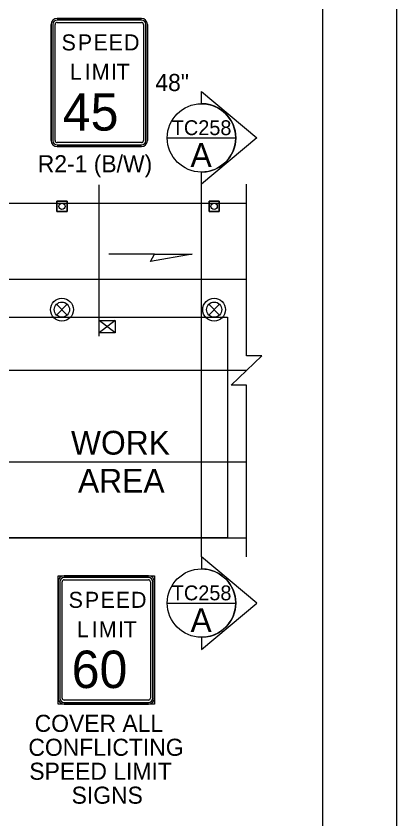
# Model space of a CAD drawing. Extents: x 99999 to 100116, y 99995 to 100013.
# Drawn here: x 100094.461 to 100096.062, y 100005.607 to 100008.987 of the extents above; entities that cross this region are included whole.
import ezdxf

# ---------------------------------------------------------------- set-up
doc = ezdxf.new("R2010")
doc.units = 0
for name, color, linetype in [('RD_MK_LineEdgeYellow', 7, 'Continuous'), ('RD_MK_LineLane', 7, 'Continuous'), ('SH_GI_PlotLimits', 7, 'Continuous'), ('SH_GI_SectionCut', 7, 'Continuous'), ('SH_GI_SheetBorder', 7, 'Continuous'), ('TR_SN_ConstructionSigns', 7, 'Continuous'), ('TR_WZ_PortableSignMount5ftMinBlk-Wht', 7, 'Continuous'), ('TR_WZ_TrafficCone', 7, 'Continuous'), ('TR_WZ_TrafficSafetyDrum', 7, 'Continuous'), ('TR_WZ_WorkAreaLabel', 7, 'Continuous'), ('TR_WZ_WorkZoneDetails', 7, 'Continuous')]:
    doc.layers.add(name, color=color, linetype=linetype)

msp = doc.modelspace()

# ---------------------------------------------------------------- linework, layer by layer
at = {"layer": 'RD_MK_LineEdgeYellow'}
for p, q in [((100092.5055, 100007.8789), (100095.43, 100007.8789)), ((100088.195, 100007.1109), (100095.43, 100007.1109))]:
    msp.add_line(p, q, dxfattribs=at)
at = {"layer": 'RD_MK_LineLane'}
msp.add_lwpolyline([(100095.43, 100007.4949), (100088.195, 100007.4949)], dxfattribs=at)
at = {"layer": 'SH_GI_PlotLimits'}
msp.add_lwpolyline([(100079.0625, 99999.6875), (100096.0625, 99999.6875), (100096.0625, 100010.6875), (100079.0625, 100010.6875)], close=True, dxfattribs=at)
at = {"layer": 'SH_GI_SectionCut'}
for p, q in [((100095.2407, 100008.6178), (100095.2407, 100008.6687)), ((100095.2407, 100008.6687), (100095.4733, 100008.4738)), ((100095.4733, 100008.4738), (100095.2407, 100008.2789)), ((100095.2407, 100008.2789), (100095.2407, 100008.3298)), ((100095.2407, 100006.7109), (100095.2407, 100008.2789)), ((100095.2407, 100006.7109), (100095.2407, 100006.66)), ((100095.4733, 100006.516), (100095.2407, 100006.7109)), ((100095.2407, 100006.3211), (100095.4733, 100006.516)), ((100095.2407, 100006.372), (100095.2407, 100006.3211))]:
    msp.add_line(p, q, dxfattribs=at)
for points in [[(100095.0967, 100008.4738), (100095.3847, 100008.4738)], [(100095.0967, 100006.516), (100095.3847, 100006.516)]]:
    msp.add_lwpolyline(points, dxfattribs=at)
for centre in [(100095.2407, 100008.4738), (100095.2407, 100006.516)]:
    msp.add_circle(centre, 0.144, dxfattribs=at)
for centre in [(100095.2407, 100008.4738), (100095.2407, 100006.516)]:
    msp.add_arc(centre, 0.144, 269.9978, 90.0022, dxfattribs=at)
at = {"layer": 'SH_GI_SheetBorder'}
msp.add_line((100095.75, 100010.375), (100095.75, 100000), dxfattribs=at)
at = {"layer": 'TR_SN_ConstructionSigns'}
for p, q in [((100094.6337, 100008.9769), (100094.9881, 100008.9769)), ((100094.9881, 100008.9769), (100094.6337, 100008.9769)), ((100094.9881, 100008.9699), (100094.6337, 100008.9699)), ((100094.6337, 100008.96), (100094.9881, 100008.96)), ((100094.6084, 100008.4622), (100094.6084, 100008.9516)), ((100094.6084, 100008.9516), (100094.6084, 100008.4622)), ((100094.6154, 100008.9516), (100094.6154, 100008.4622)), ((100094.6253, 100008.4622), (100094.6253, 100008.9516)), ((100094.9965, 100008.9516), (100094.9965, 100008.4622)), ((100095.0064, 100008.4622), (100095.0064, 100008.9516)), ((100095.0134, 100008.9516), (100095.0134, 100008.4622)), ((100095.0134, 100008.4622), (100095.0134, 100008.9516)), ((100094.9881, 100008.4538), (100094.6337, 100008.4538)), ((100094.6337, 100008.4439), (100094.9881, 100008.4439)), ((100094.9881, 100008.4369), (100094.6337, 100008.4369)), ((100094.6337, 100008.4369), (100094.9881, 100008.4369)), ((100094.6633, 100006.6309), (100095.0177, 100006.6309)), ((100095.0177, 100006.6309), (100094.6633, 100006.6309)), ((100095.0177, 100006.6239), (100094.6633, 100006.6239)), ((100094.638, 100006.1162), (100094.638, 100006.6056)), ((100094.638, 100006.6056), (100094.638, 100006.1162)), ((100094.6451, 100006.6056), (100094.6451, 100006.1162)), ((100094.6549, 100006.1162), (100094.6549, 100006.6056)), ((100094.6633, 100006.614), (100095.0177, 100006.614)), ((100095.0261, 100006.6056), (100095.0261, 100006.1162)), ((100095.036, 100006.1162), (100095.036, 100006.6056)), ((100095.043, 100006.6056), (100095.043, 100006.1162)), ((100095.043, 100006.1162), (100095.043, 100006.6056)), ((100095.0177, 100006.1078), (100094.6633, 100006.1078)), ((100094.6633, 100006.0979), (100095.0177, 100006.0979)), ((100095.0177, 100006.0909), (100094.6633, 100006.0909)), ((100094.6633, 100006.0909), (100095.0177, 100006.0909))]:
    msp.add_line(p, q, dxfattribs=at)
msp.add_lwpolyline([(100094.638, 100006.6309), (100095.043, 100006.6309), (100095.043, 100006.0909), (100094.638, 100006.0909)], close=True, dxfattribs=at)
for centre, radius, start, end in [((100094.6337, 100008.9516), 0.0253, 90, 180), ((100094.6337, 100008.9516), 0.0253, 90, 180), ((100094.6337, 100008.9516), 0.0183, 90, 180), ((100094.6337, 100008.9516), 0.00844, 90, 180), ((100094.9881, 100008.9516), 0.0253, 360, 90), ((100094.9881, 100008.9516), 0.0253, 360, 90), ((100094.9881, 100008.9516), 0.0183, 0, 90), ((100094.9881, 100008.9516), 0.00844, 360, 90), ((100094.6337, 100008.4622), 0.0253, 180, 270), ((100094.6337, 100008.4622), 0.0253, 180, 270), ((100094.6337, 100008.4622), 0.0183, 180, 270), ((100094.6337, 100008.4622), 0.00844, 180, 270), ((100094.9881, 100008.4622), 0.0253, 270, 360), ((100094.9881, 100008.4622), 0.0183, 270, 360), ((100094.9881, 100008.4622), 0.00844, 270, 0), ((100094.9881, 100008.4622), 0.0253, 270, 360), ((100094.6633, 100006.6056), 0.0253, 90, 180), ((100094.6633, 100006.6056), 0.0253, 90, 180), ((100094.6633, 100006.6056), 0.0183, 90, 180), ((100095.0177, 100006.6056), 0.0253, 0, 90), ((100095.0177, 100006.6056), 0.0253, 360, 90), ((100095.0177, 100006.6056), 0.0183, 0, 90), ((100094.6633, 100006.6056), 0.00844, 90, 180), ((100095.0177, 100006.6056), 0.00844, 360, 90), ((100094.6633, 100006.1162), 0.0253, 180, 270), ((100094.6633, 100006.1162), 0.0253, 180, 270), ((100094.6633, 100006.1162), 0.0183, 180, 270), ((100094.6633, 100006.1162), 0.00844, 180, 270), ((100095.0177, 100006.1162), 0.0253, 270, 0), ((100095.0177, 100006.1162), 0.0183, 270, 360), ((100095.0177, 100006.1162), 0.00844, 270, 0), ((100095.0177, 100006.1162), 0.0253, 270, 0)]:
    msp.add_arc(centre, radius, start, end, dxfattribs=at)
at = {"layer": 'TR_WZ_PortableSignMount5ftMinBlk-Wht'}
for p, q in [((100094.8109, 100007.6389), (100094.8109, 100007.7189)), ((100094.8776, 100007.7049), (100094.8109, 100007.6529)), ((100094.8776, 100007.6529), (100094.8109, 100007.7049)), ((100094.8443, 100007.6789), (100094.8443, 100007.6789)), ((100094.8444, 100007.679), (100094.8444, 100007.679))]:
    msp.add_line(p, q, dxfattribs=at)
msp.add_lwpolyline([(100094.8776, 100007.7049), (100094.8776, 100007.6529), (100094.8109, 100007.6529), (100094.8109, 100007.7049)], close=True, dxfattribs=at)
at = {"layer": 'TR_WZ_TrafficCone'}
for points in [[(100094.6326, 100008.1642), (100094.6753, 100008.1642), (100094.6753, 100008.2069), (100094.6326, 100008.2069), (100094.6326, 100008.1642)], [(100094.6326, 100008.2069), (100094.6753, 100008.2069), (100094.6753, 100008.1642), (100094.6326, 100008.1642), (100094.6326, 100008.2069)], [(100095.2726, 100008.1642), (100095.3153, 100008.1642), (100095.3153, 100008.2069), (100095.2726, 100008.2069), (100095.2726, 100008.1642)], [(100095.2726, 100008.2069), (100095.3153, 100008.2069), (100095.3153, 100008.1642), (100095.2726, 100008.1642), (100095.2726, 100008.2069)]]:
    msp.add_lwpolyline(points, dxfattribs=at)
for centre in [(100094.6539, 100008.1856), (100095.2939, 100008.1856)]:
    msp.add_circle(centre, 0.0133, dxfattribs=at)
at = {"layer": 'TR_WZ_TrafficSafetyDrum'}
for p, q in [((100094.6313, 100007.7735), (100094.6765, 100007.7283)), ((100094.6765, 100007.7735), (100094.6313, 100007.7283)), ((100095.2713, 100007.7735), (100095.3165, 100007.7283)), ((100095.3165, 100007.7735), (100095.2713, 100007.7283))]:
    msp.add_line(p, q, dxfattribs=at)
for centre, radius in [((100094.6539, 100007.7509), 0.048), ((100094.6539, 100007.7509), 0.048), ((100094.6539, 100007.7509), 0.032), ((100095.2939, 100007.7509), 0.048), ((100095.2939, 100007.7509), 0.048), ((100095.2939, 100007.7509), 0.032)]:
    msp.add_circle(centre, radius, dxfattribs=at)
at = {"layer": 'TR_WZ_WorkZoneDetails'}
for p, q in [((100094.8109, 100007.7111), (100094.8109, 100008.2769)), ((100092.225, 100008.1989), (100095.43, 100008.1989)), ((100095.0436, 100007.985), (100094.8508, 100007.985)), ((100088.195, 100006.7909), (100095.43, 100006.7909))]:
    msp.add_line(p, q, dxfattribs=at)
msp.add_lwpolyline([(100095.43, 100006.7109), (100095.43, 100007.433), (100095.366, 100007.433), (100095.494, 100007.5569), (100095.43, 100007.5569), (100095.43, 100008.2789)], dxfattribs=at)
for points in [[(100095.2009, 100007.985), (100095.0258, 100007.9541), (100095.0436, 100007.985)], [(100088.275, 100006.7909), (100088.275, 100007.7189), (100088.8939, 100007.7189), (100089.7339, 100007.4309), (100089.7339, 100007.4309), (100089.7339, 100007.4309), (100089.7339, 100007.4309), (100089.7339, 100007.4309), (100089.7339, 100007.4309), (100089.7339, 100007.4309), (100093.3739, 100007.4309), (100094.3814, 100007.7189), (100095.35, 100007.7189), (100095.35, 100007.2709), (100095.35, 100006.7909)]]:
    msp.add_lwpolyline(points, close=True, dxfattribs=at)

# ---------------------------------------------------------------- texts
at = {"layer": 'SH_GI_SectionCut'}
for p in [(100095.1158, 100008.4854), (100095.1158, 100006.5276)]:
    msp.add_text('TC258', height=0.0625, dxfattribs=at).set_placement(p)
for p in [(100095.1945, 100008.3518), (100095.1945, 100006.394)]:
    msp.add_text('A', height=0.1, rotation=359.99, dxfattribs=at).set_placement(p)
at = {"layer": 'TR_SN_ConstructionSigns'}
for s, height, p in [('S', 0.0675, (100094.6523, 100008.8419)), ('P', 0.0675, (100094.7205, 100008.8419)), ('E', 0.0675, (100094.7866, 100008.8419)), ('E', 0.0675, (100094.8507, 100008.8419)), ('D', 0.0675, (100094.9149, 100008.8419)), ('L', 0.0675, (100094.6874, 100008.7182)), ('I', 0.0675, (100094.7495, 100008.7182)), ('M', 0.0675, (100094.7792, 100008.7182)), ('I', 0.0675, (100094.8602, 100008.7182)), ('T', 0.0675, (100094.8838, 100008.7182)), ('48"', 0.072, (100095.0467, 100008.6709)), ('R2-1 (B/W)', 0.072, (100094.5522, 100008.3289))]:
    msp.add_text(s, height=height, rotation=360, dxfattribs=at).set_placement(p)
for s, height, p in [('45', 0.1575, (100094.6574, 100008.5044)), ('S', 0.0675, (100094.6819, 100006.4959)), ('P', 0.0675, (100094.7501, 100006.4959)), ('E', 0.0675, (100094.8162, 100006.4959)), ('E', 0.0675, (100094.8803, 100006.4959)), ('D', 0.0675, (100094.9445, 100006.4959)), ('L', 0.0675, (100094.717, 100006.3722)), ('I', 0.0675, (100094.7791, 100006.3722)), ('M', 0.0675, (100094.8088, 100006.3722)), ('I', 0.0675, (100094.8898, 100006.3722)), ('T', 0.0675, (100094.9134, 100006.3722)), ('60', 0.1575, (100094.6949, 100006.1584)), ('COVER ALL', 0.072, (100094.5392, 100005.9739)), ('CONFLICTING', 0.072, (100094.5128, 100005.8731)), ('SPEED LIMIT', 0.072, (100094.5168, 100005.7723)), ('SIGNS', 0.072, (100094.6947, 100005.6715))]:
    msp.add_text(s, height=height, dxfattribs=at).set_placement(p)
at = {"layer": 'TR_WZ_WorkAreaLabel'}
for s, p in [('WORK', (100094.6919, 100007.1409)), ('AREA', (100094.7215, 100006.9809))]:
    msp.add_text(s, height=0.1, dxfattribs=at).set_placement(p)

doc.saveas('drawing.dxf')
